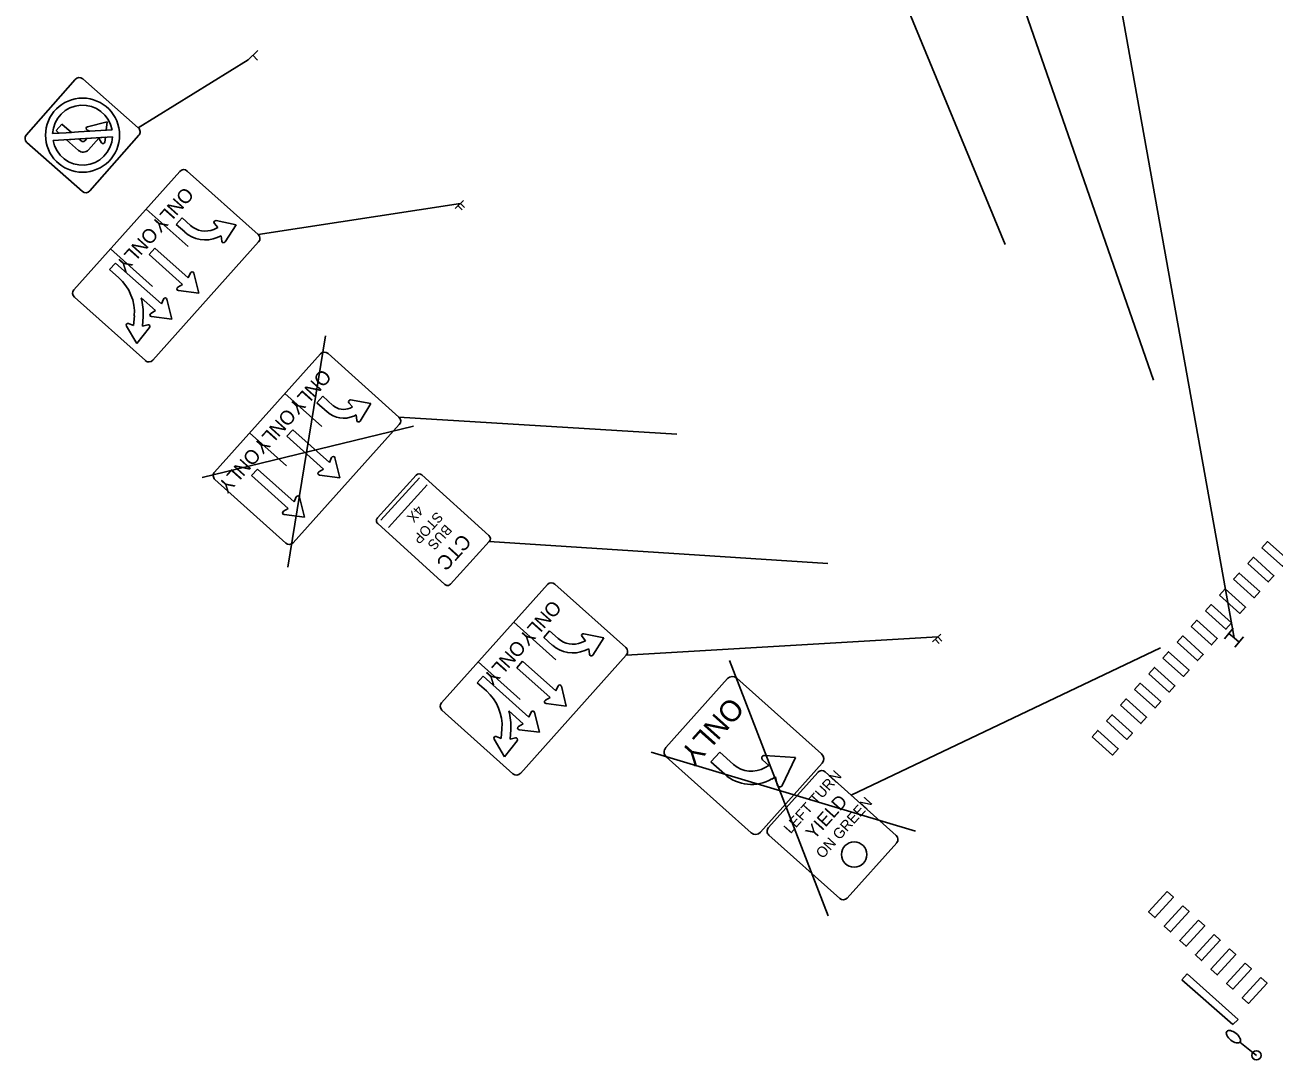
# Model space of a CAD drawing. Extents: x 1472333 to 1475205, y 385587 to 386650.
# Drawn here: x 1472849 to 1473144.2, y 385722 to 385966.6 of the extents above; entities that cross this region are included whole.
import ezdxf

# ---------------------------------------------------------------- set-up
doc = ezdxf.new("R2010")
doc.units = 0
for name, color, linetype in [('_CIVIL_CONSTRUCTION', 7, 'Continuous'), ('RS_Raster1', 7, 'Continuous'), ('RW_X_CL', 7, 'Continuous'), ('RW_X_CL_500_Cardinal_Points', 7, 'Continuous'), ('RW_X_CL_500_Stations', 7, 'Continuous'), ('SC_Scratch1', 7, 'Continuous')]:
    doc.layers.add(name, color=color, linetype=linetype)

msp = doc.modelspace()

# ---------------------------------------------------------------- linework, layer by layer
at = {"layer": '_CIVIL_CONSTRUCTION'}
for p, q in [((1472950.57, 385923.23), (1472952.56, 385925.08)), ((1472887.5, 385914.21), (1472877.56, 385923.1)), ((1472951.86, 385924.43), (1472904.05, 385917.08)), ((1472951.27, 385923.88), (1472952.19, 385922.88)), ((1472951.57, 385924.15), (1472951.57, 385924.15)), ((1472951.57, 385924.15), (1472951.57, 385924.15)), ((1472951.86, 385924.43), (1472952.79, 385923.43)), ((1472884.66, 385919.47), (1472886.05, 385921.02)), ((1472886.68, 385917.67), (1472884.66, 385919.47)), ((1472886.05, 385921.02), (1472888.07, 385919.22)), ((1472894.52, 385918.7), (1472893.69, 385919.69)), ((1472894.1, 385920.36), (1472898.83, 385919.37)), ((1472898.83, 385919.37), (1472896.21, 385915.31)), ((1472893.55, 385918.29), (1472894.52, 385918.7)), ((1472895.33, 385916.78), (1472894.35, 385916.37)), ((1472895.45, 385915.5), (1472895.33, 385916.78)), ((1472879.09, 385904.81), (1472869.16, 385913.7)), ((1472879.66, 385913.88), (1472878.27, 385912.33)), ((1472887.53, 385906.84), (1472879.66, 385913.88)), ((1472870.34, 385910.34), (1472868.95, 385908.79)), ((1472881.16, 385900.66), (1472870.34, 385910.34)), ((1472878.27, 385912.33), (1472886.14, 385905.29)), ((1472868.95, 385908.79), (1472871.12, 385906.84)), ((1472888.06, 385908.01), (1472887.53, 385906.84)), ((1472889.99, 385903.24), (1472888.84, 385907.94)), ((1472886.14, 385905.29), (1472885.03, 385904.63)), ((1472876.41, 385902.11), (1472879.77, 385899.11)), ((1472881.69, 385901.83), (1472881.16, 385900.66)), ((1472883.62, 385897.06), (1472882.48, 385901.76)), ((1472885.19, 385903.86), (1472889.99, 385903.24)), ((1472879.77, 385899.11), (1472878.66, 385898.45)), ((1472872.91, 385895.45), (1472875.38, 385891.29)), ((1472874.62, 385895.58), (1472873.42, 385896.05)), ((1472874.78, 385897.87), (1472874.62, 385895.58)), ((1472876.7, 385895.44), (1472876.86, 385897.74)), ((1472877.96, 385895.75), (1472876.7, 385895.44)), ((1472878.82, 385897.67), (1472883.62, 385897.06)), ((1472875.38, 385891.29), (1472878.38, 385895.08)), ((1472911.06, 385838.5), (1472919.92, 385893.14)), ((1472940.73, 385871.82), (1472890.79, 385859.65)), ((1473132.34, 385821.54), (1473134.36, 385824.02)), ((1473133.35, 385822.78), (1473134.59, 385821.77)), ((1473135.8, 385820.78), (1473134.56, 385821.8)), ((1473136.81, 385822.03), (1473134.79, 385819.54))]:
    msp.add_line(p, q, dxfattribs=at)
for points in [[(1472885.51, 385931.99), (1472860.51, 385904.04)], [(1472904.05, 385917.08), (1472887.28, 385932.08)], [(1472879.14, 385887.37), (1472904.14, 385915.32)], [(1472860.61, 385902.27), (1472877.38, 385887.27)]]:
    msp.add_lwpolyline(points, dxfattribs=at)
for centre, radius, start, end in [((1472886.44, 385931.15), 1.25, 48.1835, 138.1835), ((1472891.54, 385923.1), 5.21, 228.1835, 292.7008), ((1472894.01, 385919.96), 0.417, 78.1846, 220.0627), ((1472891.54, 385923.1), 7.29, 228.1835, 292.7008), ((1472903.21, 385916.15), 1.25, 318.1835, 48.1835), ((1472895.86, 385915.54), 0.417, 185.339, 327.2171), ((1472888.44, 385907.84), 0.417, 13.6673, 155.5454), ((1472863.76, 385898.61), 11.04, 356.1692, 48.1835), ((1472885.25, 385904.27), 0.417, 120.8217, 262.6998), ((1472861.44, 385903.2), 1.25, 138.1835, 228.1835), ((1472863.76, 385898.61), 13.12, 356.1692, 15.458), ((1472882.07, 385901.66), 0.417, 13.6673, 155.5454), ((1472878.88, 385898.09), 0.417, 120.8217, 262.6998), ((1472873.27, 385895.66), 0.417, 68.8074, 210.6855), ((1472878.05, 385895.34), 0.417, 321.653, 103.5311), ((1472878.21, 385888.2), 1.25, 228.1835, 318.1835)]:
    msp.add_arc(centre, radius, start, end, dxfattribs=at)
at = {"layer": 'RS_Raster1'}
for p, q in [((1473122.24, 385740.96), (1473123.47, 385742.38)), ((1473123.47, 385742.38), (1473135.56, 385731.6)), ((1473134.31, 385730.43), (1473122.24, 385740.96)), ((1473135.56, 385731.6), (1473134.31, 385730.43))]:
    msp.add_line(p, q, dxfattribs=at)
at = {"layer": 'RW_X_CL'}
for p, q in [((1473040.78, 386011.06), (1473080.47, 385914.7)), ((1473082.62, 385977.39), (1473115.53, 385882.62)), ((1472901.65, 385958.37), (1472903.97, 385960.58)), ((1472875.72, 385942.28), (1472901.65, 385958.37)), ((1472902.81, 385959.47), (1472903.91, 385958.31)), ((1472856.28, 385941.62), (1472857.65, 385943.18)), ((1472857.65, 385943.18), (1472856.28, 385941.62)), ((1472859.9, 385941.21), (1472857.65, 385943.18)), ((1472859.9, 385941.21), (1472857.65, 385943.18)), ((1472863.71, 385942.54), (1472868.4, 385943.73)), ((1472868.4, 385943.73), (1472863.71, 385942.54)), ((1472868.16, 385941.74), (1472868.4, 385943.73)), ((1472868.16, 385941.74), (1472868.4, 385943.73)), ((1472869.62, 385940.17), (1472855.58, 385939.26)), ((1472856.96, 385941.02), (1472856.28, 385941.62)), ((1472856.28, 385941.62), (1472856.96, 385941.02)), ((1472856.96, 385941.02), (1472858.7, 385941.13)), ((1472858.7, 385941.13), (1472859.9, 385941.21)), ((1472861.67, 385939.65), (1472858.81, 385939.47)), ((1472862.21, 385939.18), (1472861.67, 385939.65)), ((1472862.21, 385939.18), (1472861.67, 385939.65)), ((1472863.06, 385939.23), (1472863.54, 385939.78)), ((1472863.54, 385939.78), (1472863.06, 385939.23)), ((1472867.96, 385940.06), (1472863.54, 385939.78)), ((1472863.64, 385941.76), (1472864.23, 385941.5)), ((1472863.64, 385941.76), (1472864.23, 385941.5)), ((1472863.95, 385937.09), (1472866.38, 385939.86)), ((1472863.95, 385937.09), (1472866.38, 385939.86)), ((1472864.23, 385941.49), (1472868.16, 385941.74)), ((1472867.06, 385938.76), (1472866.38, 385939.86)), ((1472866.38, 385939.86), (1472867.06, 385938.76)), ((1472867.82, 385938.93), (1472867.96, 385940.06)), ((1472867.82, 385938.93), (1472867.96, 385940.06)), ((1472858.81, 385939.47), (1472858.73, 385939.46)), ((1472861.6, 385936.94), (1472858.73, 385939.46)), ((1472858.73, 385939.46), (1472861.6, 385936.94)), ((1472919.04, 385871.69), (1472910.35, 385879.48)), ((1472919.31, 385878.86), (1472917.92, 385877.31)), ((1472921.71, 385876.7), (1472919.31, 385878.86)), ((1472930.62, 385877.11), (1472925.86, 385877.98)), ((1472917.92, 385877.31), (1472920.32, 385875.15)), ((1472925.48, 385877.3), (1472926.33, 385876.33)), ((1472926.33, 385876.33), (1472925.75, 385876.07)), ((1472928.1, 385872.98), (1472930.62, 385877.11)), ((1472926.6, 385874.17), (1472927.18, 385874.43)), ((1472927.18, 385874.43), (1472927.33, 385873.15)), ((1472937.28, 385873.93), (1473002.97, 385869.91)), ((1472910.69, 385862.39), (1472902, 385870.18)), ((1472910.82, 385869.4), (1472912.22, 385870.95)), ((1472919.46, 385861.65), (1472910.82, 385869.4)), ((1472912.22, 385870.95), (1472920.85, 385863.2)), ((1472920.85, 385863.2), (1472921.39, 385864.38)), ((1472922.17, 385864.3), (1472923.3, 385859.6)), ((1472902.48, 385860.1), (1472903.87, 385861.65)), ((1472911.11, 385852.35), (1472902.48, 385860.1)), ((1472903.87, 385861.65), (1472912.5, 385853.9)), ((1472918.35, 385860.99), (1472919.46, 385861.65)), ((1472923.3, 385859.6), (1472918.51, 385860.22)), ((1472932.98, 385849.54), (1472942.12, 385859.61)), ((1472934.84, 385847.86), (1472943.97, 385857.93)), ((1472912.5, 385853.9), (1472913.04, 385855.07)), ((1472913.82, 385855), (1472914.96, 385850.3)), ((1472910, 385851.69), (1472911.11, 385852.35)), ((1472914.96, 385850.3), (1472910.16, 385850.92)), ((1472958.63, 385844.54), (1473038.61, 385839.31))]:
    msp.add_line(p, q, dxfattribs=at)
for points in [[(1472849.26, 385940.57), (1472860.81, 385953.72)], [(1472862.58, 385953.83), (1472875.72, 385942.28)], [(1472858.7, 385941.13), (1472855.48, 385940.92)], [(1472869.51, 385941.83), (1472861.56, 385941.32), (1472858.7, 385941.13)], [(1472864.23, 385941.5), (1472864.23, 385941.49)], [(1472875.84, 385940.52), (1472864.29, 385927.37)], [(1472862.52, 385927.26), (1472849.38, 385938.81)], [(1472893.73, 385860.95), (1472918.77, 385888.86)], [(1472920.53, 385888.96), (1472937.28, 385873.93)], [(1472937.38, 385872.17), (1472912.33, 385844.25)], [(1472932.22, 385850.13), (1472941.36, 385860.21)], [(1472942.73, 385860.28), (1472958.56, 385845.92)], [(1472910.57, 385844.16), (1472893.82, 385859.18)], [(1472948.12, 385834.4), (1472932.28, 385848.76)], [(1472958.63, 385844.54), (1472949.49, 385834.47)]]:
    msp.add_lwpolyline(points, dxfattribs=at)
msp.add_circle((1472862.55, 385940.55), 8.75, dxfattribs=at)
for centre, radius, start, end in [((1472861.75, 385952.9), 1.25, 48.7, 138.7), ((1472862.55, 385940.55), 7.08, 10.4563, 176.9437), ((1472862.55, 385940.55), 7.08, 10.4563, 176.9437), ((1472863.81, 385942.14), 0.417, 104.1837, 246.0618), ((1472863.81, 385942.14), 0.417, 104.1837, 246.0618), ((1472850.2, 385939.75), 1.25, 138.7, 228.7), ((1472862.55, 385940.55), 7.08, 190.4563, 356.9437), ((1472874.9, 385941.34), 1.25, 318.7, 48.7), ((1472862.7, 385938.19), 1.67, 228.7, 318.7), ((1472862.7, 385938.19), 1.67, 228.7, 318.7), ((1472862.61, 385939.63), 0.6, 228.7, 318.7), ((1472862.61, 385939.63), 0.6, 228.7, 318.7), ((1472867.41, 385938.98), 0.417, 211.3382, 353.2163), ((1472867.41, 385938.98), 0.417, 211.3382, 353.2163), ((1472863.35, 385928.2), 1.25, 228.7, 318.7), ((1472919.7, 385888.03), 1.25, 48.1, 138.1), ((1472925.79, 385877.57), 0.417, 79.6271, 221.5052), ((1472924.22, 385879.49), 5.83, 228.1, 294.1899), ((1472924.22, 385879.49), 3.75, 228.1, 294.2014), ((1472927.75, 385873.2), 0.417, 186.7816, 328.6597), ((1472936.45, 385873), 1.25, 318.1, 48.1), ((1472921.76, 385864.2), 0.417, 13.5837, 155.4618), ((1472894.66, 385860.12), 1.25, 138.1, 228.1), ((1472918.56, 385860.64), 0.417, 120.7382, 262.6163), ((1472942.08, 385859.56), 0.972, 47.7891, 137.7891), ((1472913.42, 385854.9), 0.417, 13.5837, 155.4618), ((1472910.22, 385851.33), 0.417, 120.7382, 262.6163), ((1472932.94, 385849.48), 0.972, 137.7891, 227.7891), ((1472957.91, 385845.2), 0.972, 317.7891, 47.7891), ((1472911.4, 385845.09), 1.25, 228.1, 318.1), ((1472948.77, 385835.12), 0.972, 227.7891, 317.7891)]:
    msp.add_arc(centre, radius, start, end, dxfattribs=at)
at = {"layer": 'RW_X_CL_500_Cardinal_Points'}
for p, q in [((1473105.79, 385982.46), (1473134.57, 385821.78)), ((1472974.34, 385816.59), (1472964.41, 385825.48)), ((1472971.51, 385821.86), (1472972.89, 385823.41)), ((1472973.52, 385820.05), (1472971.51, 385821.86)), ((1472972.89, 385823.41), (1472974.91, 385821.6)), ((1472981.37, 385821.09), (1472980.54, 385822.07)), ((1472980.94, 385822.75), (1472985.67, 385821.76)), ((1472985.67, 385821.76), (1472983.06, 385817.7)), ((1473064.59, 385822.01), (1472990.99, 385817.7)), ((1473063.3, 385820.81), (1473065.29, 385822.65)), ((1473063.99, 385821.45), (1473064.92, 385820.45)), ((1473064.29, 385821.73), (1473064.29, 385821.73)), ((1473064.29, 385821.73), (1473064.29, 385821.73)), ((1473064.59, 385822.01), (1473065.52, 385821.01)), ((1472980.4, 385820.68), (1472981.37, 385821.09)), ((1472982.17, 385819.17), (1472981.2, 385818.76)), ((1472982.29, 385817.88), (1472982.17, 385819.17)), ((1473044.14, 385784.6), (1473117.16, 385819.4)), ((1472965.94, 385807.2), (1472956, 385816.09)), ((1472966.5, 385816.27), (1472965.12, 385814.71)), ((1472974.37, 385809.23), (1472966.5, 385816.27)), ((1473015.39, 385816.42), (1473038.7, 385756.11)), ((1472957.19, 385812.72), (1472955.8, 385811.17)), ((1472968.01, 385803.04), (1472957.19, 385812.72)), ((1472965.12, 385814.71), (1472972.99, 385807.67)), ((1472955.8, 385811.17), (1472957.97, 385809.23)), ((1472974.91, 385810.4), (1472974.37, 385809.23)), ((1472976.83, 385805.63), (1472975.69, 385810.33)), ((1472972.99, 385807.67), (1472971.88, 385807.01)), ((1472963.26, 385804.5), (1472966.62, 385801.49)), ((1472968.54, 385804.22), (1472968.01, 385803.04)), ((1472970.47, 385799.45), (1472969.32, 385804.14)), ((1472972.04, 385806.24), (1472976.83, 385805.63)), ((1472966.62, 385801.49), (1472965.51, 385800.83)), ((1472959.76, 385797.83), (1472962.23, 385793.68)), ((1472961.47, 385797.97), (1472960.27, 385798.44)), ((1472961.63, 385800.26), (1472961.47, 385797.97)), ((1472963.55, 385797.83), (1472963.7, 385800.12)), ((1472964.8, 385798.13), (1472963.55, 385797.83)), ((1472965.67, 385800.06), (1472970.47, 385799.45)), ((1472962.23, 385793.68), (1472965.23, 385797.47)), ((1473059.34, 385776.11), (1472996.91, 385794.77)), ((1473013.07, 385794.77), (1473010.99, 385792.44)), ((1473010.99, 385792.44), (1473014.25, 385789.53)), ((1473016.34, 385791.86), (1473013.07, 385794.77)), ((1473023.21, 385792.91), (1473024.64, 385791.61)), ((1473030.93, 385793.49), (1473023.67, 385794)), ((1473027.83, 385786.91), (1473030.93, 385793.49)), ((1473024.64, 385791.61), (1473023.78, 385791.11)), ((1473025.36, 385788.41), (1473026.22, 385788.92)), ((1473026.22, 385788.92), (1473026.65, 385787.03))]:
    msp.add_line(p, q, dxfattribs=at)
for points in [[(1472972.36, 385834.37), (1472947.36, 385806.42)], [(1472990.89, 385819.47), (1472974.12, 385834.47)], [(1472965.99, 385789.75), (1472990.99, 385817.7)], [(1473014.91, 385812.14), (1473000.33, 385795.83)], [(1473037.15, 385794.35), (1473017.11, 385812.26)], [(1472947.45, 385804.66), (1472964.22, 385789.66)], [(1473000.45, 385793.63), (1473020.48, 385775.71)], [(1473022.69, 385775.84), (1473037.27, 385792.14)], [(1473024.57, 385776.95), (1473036.23, 385789.99)], [(1473037.99, 385790.09), (1473054.77, 385775.09)], [(1473041.44, 385760.18), (1473024.66, 385775.18)], [(1473054.87, 385773.33), (1473043.2, 385760.28)]]:
    msp.add_lwpolyline(points, dxfattribs=at)
msp.add_circle((1473044.83, 385770.57), 3, dxfattribs=at)
for centre, radius, start, end in [((1472973.29, 385833.54), 1.25, 48.1835, 138.1835), ((1472978.39, 385825.49), 5.21, 228.1835, 292.7008), ((1472980.86, 385822.34), 0.417, 78.1846, 220.0627), ((1472978.39, 385825.49), 7.29, 228.1835, 292.7008), ((1472990.06, 385818.54), 1.25, 318.1835, 48.1835), ((1472982.71, 385817.92), 0.417, 185.339, 327.2171), ((1473016.07, 385811.1), 1.56, 48.2, 138.2), ((1472975.29, 385810.23), 0.417, 13.6673, 155.5454), ((1472950.61, 385801), 11.04, 356.1692, 48.1835), ((1472972.09, 385806.66), 0.417, 120.8217, 262.6998), ((1472948.29, 385805.59), 1.25, 138.1835, 228.1835), ((1472950.61, 385801), 13.12, 356.1692, 15.458), ((1472968.92, 385804.05), 0.417, 13.6673, 155.5454), ((1472965.72, 385800.47), 0.417, 120.8217, 262.6998), ((1472960.12, 385798.05), 0.417, 68.8074, 210.6855), ((1472964.9, 385797.73), 0.417, 321.653, 103.5311), ((1473001.49, 385794.79), 1.56, 138.2, 228.2), ((1473023.63, 385793.38), 0.625, 85.9543, 227.726), ((1473036.11, 385793.18), 1.56, 318.2, 48.2), ((1472965.06, 385790.59), 1.25, 228.1835, 318.1835), ((1473020.57, 385796.6), 9.48, 228.2, 300.3425), ((1473020.57, 385796.6), 6.35, 228.2, 300.3387), ((1473037.16, 385789.16), 1.25, 48.2, 138.2), ((1473027.26, 385787.17), 0.625, 192.9936, 334.7653), ((1473021.53, 385776.88), 1.56, 228.2, 318.2), ((1473025.5, 385776.11), 1.25, 138.2, 228.2), ((1473053.93, 385774.16), 1.25, 318.2, 48.2), ((1473042.27, 385761.12), 1.25, 228.2, 318.2)]:
    msp.add_arc(centre, radius, start, end, dxfattribs=at)
at = {"layer": 'RW_X_CL_500_Stations'}
msp.add_line((1473139.86, 385723.12), (1473135.97, 385726.26), dxfattribs=at)
msp.add_circle((1473139.86, 385723.12), 1.1, dxfattribs=at)
msp.add_ellipse((1473134.42, 385727.52), major_axis=(-1.56, 1.26), ratio=0.5, dxfattribs=at)
at = {"layer": 'SC_Scratch1'}
for points in [[(1473141.16, 385843.04), (1473145.99, 385838.69), (1473147.33, 385840.18), (1473142.49, 385844.52)], [(1473137.82, 385839.32), (1473142.65, 385834.97), (1473143.99, 385836.46), (1473139.15, 385840.81)], [(1473134.47, 385835.6), (1473139.31, 385831.25), (1473140.65, 385832.74), (1473135.81, 385837.09)], [(1473131.13, 385831.88), (1473135.97, 385827.53), (1473137.3, 385829.02), (1473132.47, 385833.37)], [(1473127.79, 385828.16), (1473132.63, 385823.82), (1473133.96, 385825.3), (1473129.13, 385829.65)], [(1473124.45, 385824.44), (1473129.28, 385820.1), (1473130.62, 385821.58), (1473125.79, 385825.93)], [(1473121.11, 385820.72), (1473125.94, 385816.38), (1473127.28, 385817.86), (1473122.44, 385822.21)], [(1473117.77, 385817), (1473122.6, 385812.66), (1473123.94, 385814.15), (1473119.1, 385818.49)], [(1473114.42, 385813.28), (1473119.26, 385808.94), (1473120.6, 385810.43), (1473115.76, 385814.77)], [(1473111.08, 385809.56), (1473115.92, 385805.22), (1473117.25, 385806.71), (1473112.42, 385811.05)], [(1473107.74, 385805.84), (1473112.58, 385801.5), (1473113.91, 385802.99), (1473109.08, 385807.33)], [(1473104.4, 385802.13), (1473109.23, 385797.78), (1473110.57, 385799.27), (1473105.74, 385803.61)], [(1473101.06, 385798.41), (1473105.89, 385794.06), (1473107.23, 385795.55), (1473102.39, 385799.89)], [(1473118.79, 385761.81), (1473114.39, 385757.02), (1473115.87, 385755.67), (1473120.26, 385760.46)], [(1473122.47, 385758.43), (1473118.08, 385753.64), (1473119.55, 385752.29), (1473123.94, 385757.07)], [(1473126.15, 385755.05), (1473121.76, 385750.26), (1473123.23, 385748.9), (1473127.63, 385753.69)], [(1473129.84, 385751.66), (1473125.44, 385746.88), (1473126.91, 385745.52), (1473131.31, 385750.31)], [(1473133.52, 385748.28), (1473129.12, 385743.49), (1473130.6, 385742.14), (1473134.99, 385746.93)], [(1473137.2, 385744.9), (1473132.81, 385740.11), (1473134.28, 385738.76), (1473138.68, 385743.55)], [(1473140.89, 385741.52), (1473136.49, 385736.73), (1473137.96, 385735.38), (1473142.36, 385740.17)]]:
    msp.add_lwpolyline(points, close=True, dxfattribs=at)

# ---------------------------------------------------------------- texts
at = {"layer": '_CIVIL_CONSTRUCTION'}
for p in [(1472886.63, 385928.55), (1472878.23, 385919.15)]:
    msp.add_text('ONLY', height=3.333, rotation=228.1835, dxfattribs=at).set_placement(p)
at = {"layer": 'RW_X_CL'}
for s, height, rotation, p in [('ONLY', 3.333, 228.1, (1472919.14, 385885.53)), ('ONLY', 3.333, 228.1, (1472910.79, 385876.23)), ('ONLY', 3.333, 228.1, (1472902.44, 385866.92)), ('4X', 2.38, 227.7891, (1472941.61, 385853.28)), ('STOP', 2.38, 227.7891, (1472946.18, 385851.75)), ('BUS', 2.38, 227.7891, (1472948.28, 385848.75)), ('CTC', 3.4, 227.7891, (1472952.16, 385846.59))]:
    msp.add_text(s, height=height, rotation=rotation, dxfattribs=at).set_placement(p)
at = {"layer": 'RW_X_CL_500_Cardinal_Points'}
for s, height, rotation, p in [('ONLY', 3.333, 228.1835, (1472973.48, 385830.93)), ('ONLY', 3.333, 228.1835, (1472965.07, 385821.54)), ('ONLY', 5, 228.2, (1473015.51, 385808.12)), ('LEFT TURN', 2.503, 48.2, (1473029.8, 385775.33)), ('YIELD', 3.128, 48.2, (1473035.41, 385773.94)), ('ON GREEN', 2.503, 48.2, (1473037.4, 385769.43))]:
    msp.add_text(s, height=height, rotation=rotation, dxfattribs=at).set_placement(p)

doc.saveas('drawing.dxf')
